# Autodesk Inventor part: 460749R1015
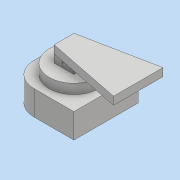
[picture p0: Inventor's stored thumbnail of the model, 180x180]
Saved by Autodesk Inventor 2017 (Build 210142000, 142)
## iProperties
Created: 2016-07
Part Number: 460749R1015
Material: Generic
Document SubType Name: Modeling
Designer: Polytech
Density: 1 g/cm^3
Appearance: Default
Author: Polytech
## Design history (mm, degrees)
sketch "Sketch1"
  geometry: C1 r 23 at (0, 0); 1 further point
  constraints: 1 centre point, 1 coincident
  dimensions: "d0" = 46 diameter of C1
extrude "Extrusion1" new body sketch "Sketch1" distance "d1" = 18; taper "d2" = 0 deg
sketch "Sketch2"
  geometry: L1 (-11.75, 48.75)-(48.75, 48.75); L2 (48.75, 48.75)-(48.75, -48.75); L3 (48.75, -48.75)-(-11.75, -48.75); L4 (-48.75, -11.75)-(-48.75, 11.75); L5 (-48.75, 48.75)-(48.75, -48.75); L6 (48.75, 48.75)-(-48.75, -48.75); A1 r 37 centre (-11.75, 11.75) between (-11.75, 48.75) and (-48.75, 11.75); A2 r 37 centre (-11.75, -11.75) between (-48.75, -11.75) and (-11.75, -48.75); 1 further point
  constraints: 12 end point, 4 point on circle, 4 point on line, 4 tangent, 2 centre point, 2 midpoint, 2 parallel, 1 equal radius, 1 horizontal, 1 perpendicular
  dimensions: "d3" = 97.5 distance of L2.end L6.end; "d4" = 97.5 distance of L1.end L2.end; "d5" = 37 radius of A1
extrude "Extrusion2" join sketch "Sketch2" distance "d6" = 37.5; taper "d7" = 0 deg
sketch "Sketch3"
  geometry: C1 r 37.5 at (0, 0); 1 further point
  constraints: 1 centre point, 1 coincident
  dimensions: "d8" = 75 diameter of C1
extrude "Extrusion3" join sketch "Sketch3" distance "d9" = 15; taper "d10" = 0 deg
sketch "Sketch4"
  geometry: L1 (-15, 15)-(15, 15); L2 (15, 15)-(15, -15); L3 (15, -15)-(-15, -15); L4 (-15, -15)-(-15, 15); L5 (-15, 15)-(15, -15); L6 (15, 15)-(-15, -15); 1 further point
  constraints: 12 end point, 2 midpoint, 2 parallel, 1 horizontal, 1 perpendicular
  dimensions: "d11" = 30 distance of L2.end L3.end; "d12" = 30 distance of L1.end L2.end
extrude "Extrusion4" join sketch "Sketch4" distance "d13" = 12; taper "d14" = 0 deg
sketch "Sketch5"
  geometry: L1 (-15, 6)-(15, 6); L2 (15, 6)-(15, -6); L3 (15, -6)-(-15, -6); L4 (-15, -6)-(-15, 6); L5 (-15, 6)-(15, -6); L6 (15, 6)-(-15, -6); 1 further point
  constraints: 12 end point, 2 midpoint, 2 parallel, 1 horizontal, 1 perpendicular
  dimensions: "d15" = 30 distance of L2.end L3.end; "d16" = 12 distance of L1.end L2.end
extrude "Extrusion5" cut sketch "Sketch5" distance "d17" = 12; taper "d18" = 0 deg
sketch "Sketch6"
  geometry: L1 (52.5, 0)-(-22.5, 0) reference; C1 r 3 at (15, 6); 1 further point
  constraints: 1 centre point, 1 vertical alignment
  dimensions: "d19" = 6 diameter of C1; "d20" = 6 distance from line of L1 C1.centre
extrude "Extrusion6" cut sketch "Sketch6" stored distance "d21" = 12; taper "d22" = 0 deg
sketch "Sketch7"
  geometry: L1 (-15, 15)-(-15, -15); L2 (-15, -15)-(97.5, -37.5); L3 (97.5, -37.5)-(97.5, 37.5); L4 (97.5, 37.5)-(-15, 15); 4 further points
  constraints: 8 end point, 2 coincident, 1 horizontal alignment, 1 midpoint, 1 parallel, 1 vertical
  dimensions: "d23" = 75 distance of L2.end L3.end; "d24" = 97.5 horizontal distance of L2.end point (0, 0)
extrude "Extrusion7" join sketch "Sketch7" distance "d25" = 12; taper "d26" = 0 deg
sketch "Sketch8"
  geometry: C1 r 23 at (0, 0); 1 further point
  constraints: 1 centre point, 1 coincident
  dimensions: "d27" = 46 diameter of C1
extrude "Extrusion8" cut sketch "Sketch8" distance "d28" = 24.5; taper "d29" = 0 deg
body "Solid1"
